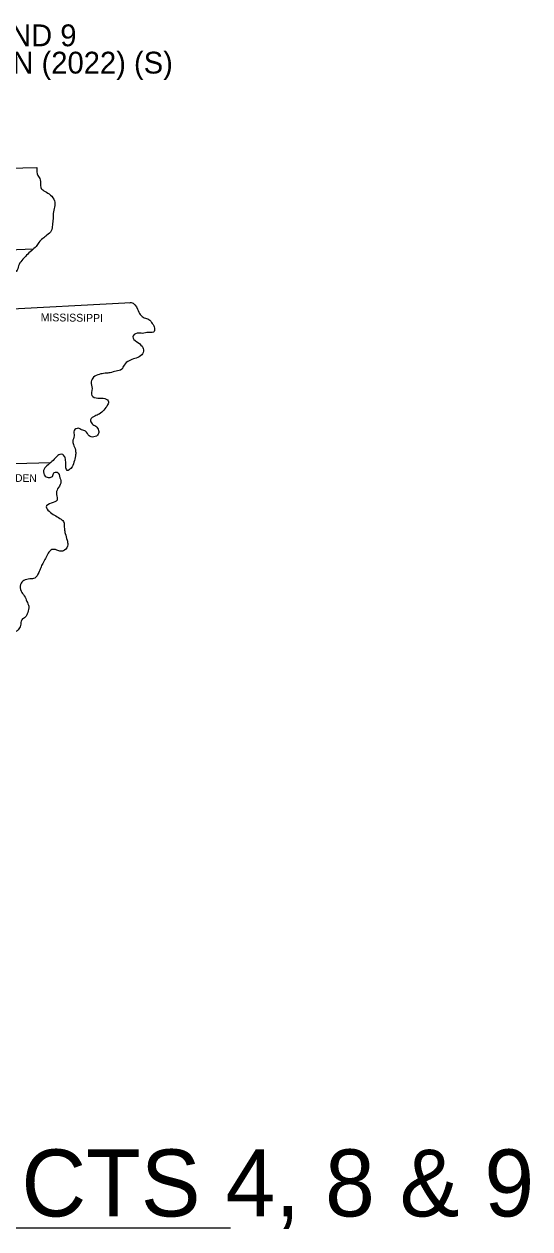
# Model space of a CAD drawing. Extents: x -13171 to 18763, y -8840 to 11152.
# Drawn here: x 16044 to 18763, y 4654 to 11129 of the extents above; entities that cross this region are included whole.
import ezdxf

# ---------------------------------------------------------------- set-up
doc = ezdxf.new("R2010")
doc.units = 0
for name, color, linetype in [('Level 1', 7, 'Continuous'), ('Level 2', 7, 'Continuous'), ('Level 42', 7, 'Continuous')]:
    doc.layers.add(name, color=color, linetype=linetype)

msp = doc.modelspace()

# ---------------------------------------------------------------- linework, layer by layer
at = {"layer": 'Level 1'}
msp.add_line((9238.8, 4659.5), (17153.7, 4659.5), dxfattribs=at)
for points in [[(10745.4, 10313), (12327.5, 10312), (13715.8, 10314.9), (15353.7, 10340.4), (16112.9, 10358)], [(15330.2, 9819.9), (15335.1, 10024.4), (15335.1, 9988.2), (15907.5, 9991.1), (15915.3, 9914.8), (16094.8, 9921.3)], [(15878.1, 9593.9), (16620.7, 9632)], [(15082.5, 8752.4), (15473.1, 8754.4), (15474, 8768.1), (15605.1, 8777.9), (15605.1, 8757.3), (16188, 8773.3)]]:
    msp.add_lwpolyline(points, dxfattribs=at)
for points in [[(16112.9, 10358), (16117.8, 10314.9), (16131.5, 10292.4), (16133.5, 10251.3), (16150.1, 10233.7), (16178.5, 10216.1), (16203.9, 10187.8), (16209.8, 10154.5), (16202, 10120.2), (16200, 10082.1), (16196.1, 10048.8), (16190.2, 10018.5), (16166.7, 9994), (16144.2, 9976.4), (16123.7, 9955.9), (16109, 9934.3), (16083.6, 9910.9), (16058.1, 9886.4), (16037.6, 9864.9), (16017, 9837.5), (16007.3, 9807.2), (15984.8, 9785.6), (15967.1, 9766.1), (15943.7, 9739.6), (15931.9, 9713.2), (15909.4, 9682.9), (15904.5, 9653.5), (15889.9, 9630.1), (15888.9, 9626.1)], [(16610, 9631), (16620.7, 9632), (16654, 9596.8), (16668.7, 9567.4), (16690.2, 9550.8), (16714.7, 9542), (16733.2, 9519.5), (16746, 9495), (16739.1, 9473.5), (16711.7, 9471.6), (16681.4, 9466.7), (16652, 9467.6), (16628.6, 9448.1), (16650.1, 9421.7), (16678.4, 9397.2), (16686.3, 9370.8), (16670.6, 9345.3), (16639.3, 9331.6), (16609, 9319.9), (16581.6, 9296.4), (16568.9, 9273.9), (16538.5, 9264.1), (16507.2, 9255.3), (16479.8, 9252.4), (16448.5, 9246.5), (16418.2, 9231.8), (16405.5, 9206.4), (16409.4, 9170.2), (16408.4, 9132.1), (16440.7, 9119.3), (16469.1, 9118.4), (16496.5, 9103.7), (16493.5, 9082.2), (16473, 9054.8), (16448.5, 9033.2), (16424.1, 9022.5), (16401.6, 9001.9), (16409.4, 8981.4), (16429.9, 8967.7), (16444.6, 8945.2), (16442.7, 8924.6), (16419.2, 8910), (16393.7, 8915.8), (16375.1, 8940.3), (16353.6, 8948.1), (16335, 8956.9), (16313.5, 8944.2), (16313.5, 8915.8), (16305.7, 8885.5), (16312.5, 8863), (16321.3, 8831.7), (16320.4, 8808.2), (16312.5, 8774.9), (16295.9, 8740.7), (16276.3, 8729.9), (16268.5, 8767.1), (16264.6, 8797.4), (16252.8, 8815), (16237.2, 8816), (16216.6, 8801.3), (16194.1, 8778.8), (16165.8, 8754.4), (16149.1, 8729.9), (16157.9, 8699.6), (16179.5, 8691.8), (16196.1, 8697.6), (16204.9, 8717.2), (16221.5, 8720.1), (16237.2, 8689.8)], [(16237.2, 8689.8), (16241.1, 8661.4), (16224.5, 8631.1), (16218.6, 8600.8), (16221.5, 8570.4), (16190.2, 8553.8), (16162.8, 8534.2), (16178.5, 8510.8), (16207.8, 8489.2), (16237.2, 8472.6), (16255.8, 8456), (16260.7, 8415.9), (16265.6, 8390.4), (16275.3, 8355.2), (16279.3, 8330.7), (16261.6, 8301.4), (16241.1, 8295.5), (16219.6, 8302.4), (16194.1, 8304.3), (16173.6, 8284.8), (16158.9, 8257.4), (16144.2, 8230), (16133.5, 8206.5), (16122.7, 8181), (16101.2, 8151.7), (16074.8, 8146.8), (16043.5, 8139), (16024.9, 8117.4), (16027.8, 8081.2), (16045.4, 8056.8), (16059.1, 8026.5), (16068.9, 8000), (16064, 7966.8), (16050.3, 7942.3), (16032.7, 7927.6), (16024.9, 7896.3), (16012.2, 7872.8), (16000.4, 7865), (15976.9, 7867), (15951.5, 7871.9), (15930, 7869.9), (15909.4, 7859.1), (15888.9, 7866), (15867.4, 7889.5), (15849.7, 7907.1), (15830.2, 7913.9), (15809.6, 7903.2), (15805.7, 7870.9), (15815.5, 7837.6), (15824.3, 7792.6), (15815.5, 7765.2), (15812.6, 7720.2)]]:
    msp.add_spline(points, degree=3, dxfattribs=at)

# ---------------------------------------------------------------- texts
at = {"layer": 'Level 2'}
for s, height, rotation, p in [('MISSISSIPPI', 42.062, 359.30972, (16133.5, 9532.2)), ('CRITTENDEN', 41.09, 359.21302, (15757.8, 8672.2))]:
    msp.add_text(s, height=height, rotation=rotation, dxfattribs=at).set_placement(p)
msp.add_text('ARKANSAS HIGHWAY DISTRICTS 4, 8 & 9', height=360, dxfattribs=at).set_placement((9262.7, 4720.5))
at = {"layer": 'Level 42'}
for s, p in [('DISTRICTS 4, 8 AND 9 ', (14688.2, 11010)), ('BRIDGE PRESERVATION (2022) (S)', (14221.7, 10863.2))]:
    msp.add_text(s, height=117.24, dxfattribs=at).set_placement(p)

doc.saveas('drawing.dxf')
